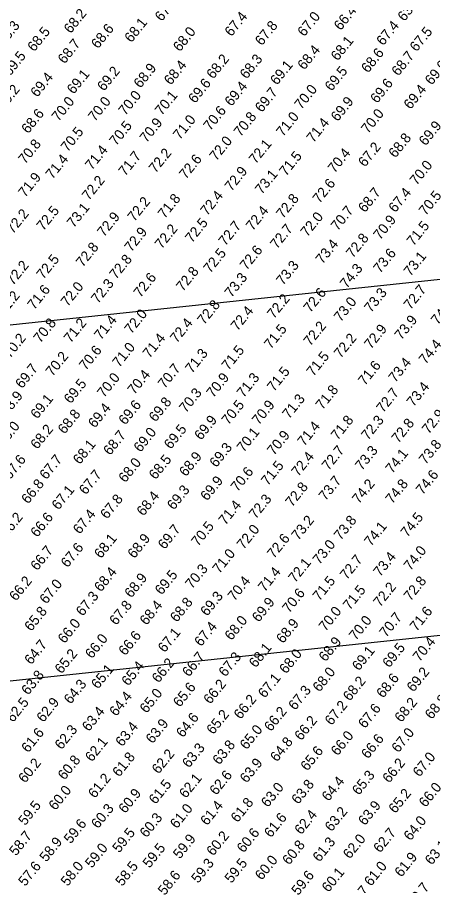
# Model space of a CAD drawing. Extents: x 401290 to 405690, y 1190598 to 1193998.
# Drawn here: x 403862 to 404273, y 1191942 to 1192801 of the extents above; entities that cross this region are included whole.
import ezdxf

# ---------------------------------------------------------------- set-up
doc = ezdxf.new("R2010")
doc.units = 0
for name, color, linetype in [('C-CHAN-CNTR', 7, 'Continuous'), ('C-CHAN-POIT', 7, 'Continuous'), ('V-TOPO-SOUN', 7, 'Continuous')]:
    doc.layers.add(name, color=color, linetype=linetype)

msp = doc.modelspace()

# ---------------------------------------------------------------- linework, layer by layer
at = {"layer": 'C-CHAN-CNTR'}
msp.add_line((401937.03, 1192293.37), (404340.86, 1192548.17), dxfattribs=at)
at = {"layer": 'C-CHAN-POIT'}
msp.add_line((402579.39, 1192009.5), (404317.15, 1192193.7), dxfattribs=at)

# ---------------------------------------------------------------- texts
at = {"layer": 'V-TOPO-SOUN'}
for s, p in [('67.9 ', (404005.19, 1192796.02)), ('63.4 ', (404245.19, 1192796.02)), ('68.2 ', (403915.2, 1192784.01)), ('67.4 ', (404074.19, 1192781.02)), ('67.0 ', (404146.2, 1192781.02)), ('66.4 ', (404182.19, 1192787.03)), ('68.1 ', (403975.17, 1192775.02)), ('67.4 ', (404224.19, 1192772.03)), ('68.3 ', (403849.19, 1192772.03)), ('68.5 ', (403879.18, 1192766.03)), ('68.6 ', (403942.2, 1192769.01)), ('68.0 ', (404023.17, 1192766.03)), ('67.8 ', (404104.18, 1192772.03)), ('67.5 ', (404257.19, 1192766.03)), ('68.7 ', (403909.2, 1192754.02)), ('68.1 ', (404179.18, 1192757.01)), ('68.4 ', (404146.2, 1192748.02)), ('69.5 ', (403855.19, 1192742.01)), ('68.2 ', (404056.18, 1192739.03)), ('68.3 ', (404089.18, 1192739.03)), ('68.6 ', (404209.19, 1192745.03)), ('68.7 ', (404239.18, 1192742.01)), ('68.9 ', (403984.2, 1192730)), ('68.4 ', (404014.18, 1192733.02)), ('69.1 ', (404119.2, 1192733.02)), ('69.0 ', (404272.19, 1192733.02)), ('69.4 ', (403882.19, 1192721.02)), ('69.1 ', (403918.19, 1192724.03)), ('69.2 ', (403948.17, 1192727.02)), ('69.5 ', (404173.17, 1192727.02)), ('69.6 ', (404038.2, 1192715.01)), ('69.4 ', (404074.19, 1192712.03)), ('69.6 ', (404218.18, 1192715.01)), ('69.2 ', (403849.19, 1192709.01)), ('69.7 ', (404104.18, 1192706.02)), ('70.0 ', (404143.18, 1192709.01)), ('69.4 ', (404251.19, 1192709.01)), ('70.0 ', (403903.19, 1192697.03)), ('70.0 ', (403939.18, 1192697.03)), ('70.0 ', (403969.2, 1192703.04)), ('70.1 ', (404005.19, 1192703.04)), ('69.9 ', (404179.18, 1192697.03)), ('70.6 ', (404053.19, 1192688.01)), ('68.6 ', (403873.17, 1192685.02)), ('71.0 ', (404023.17, 1192679.02)), ('70.8 ', (404083.18, 1192682.01)), ('71.0 ', (404125.17, 1192682.01)), ('70.0 ', (404209.19, 1192685.02)), ('70.5 ', (403960.18, 1192673.02)), ('70.9 ', (403990.2, 1192676.03)), ('71.4 ', (404155.19, 1192676.03)), ('69.9 ', (404266.18, 1192673.02)), ('70.5 ', (403912.18, 1192667.01)), ('68.8 ', (404236.2, 1192661.01)), ('70.8 ', (403870.19, 1192655)), ('72.0 ', (404059.2, 1192658.02)), ('72.1 ', (404098.17, 1192655)), ('67.2 ', (404206.18, 1192652.02)), ('71.4 ', (403936.2, 1192649.03)), ('71.7 ', (403969.2, 1192643.03)), ('72.2 ', (403999.19, 1192646.02)), ('71.5 ', (404128.19, 1192643.03)), ('70.4 ', (404176.19, 1192646.02)), ('71.4 ', (403897.19, 1192640.01)), ('72.6 ', (404029.18, 1192640.01)), ('72.9 ', (404074.19, 1192628.04)), ('70.0 ', (404257.19, 1192634.01)), ('71.9 ', (403870.19, 1192622.03)), ('72.2 ', (403933.18, 1192619.01)), ('73.1 ', (404104.18, 1192625.02)), ('72.6 ', (404161.2, 1192616.03)), ('71.8 ', (404008.18, 1192601.04)), ('72.4 ', (404050.17, 1192604.02)), ('72.8 ', (404125.17, 1192601.04)), ('68.7 ', (404206.18, 1192607.01)), ('67.4 ', (404236.2, 1192607.01)), ('70.5 ', (404266.18, 1192604.02)), ('72.2 ', (403978.19, 1192598.02)), ('72.2 ', (403858.18, 1192586.01)), ('72.5 ', (403888.2, 1192589.03)), ('73.1 ', (403918.19, 1192592.01)), ('72.4 ', (404095.19, 1192589.03)), ('70.7 ', (404179.18, 1192589.03)), ('72.9 ', (403948.17, 1192583.02)), ('72.5 ', (404035.18, 1192577.02)), ('72.7 ', (404068.18, 1192574.03)), ('72.0 ', (404149.19, 1192583.02)), ('70.9 ', (404221.2, 1192580)), ('72.9 ', (403975.17, 1192568.03)), ('72.2 ', (404005.19, 1192571.02)), ('72.7 ', (404119.2, 1192571.02)), ('71.5 ', (404254.18, 1192574.03)), ('72.8 ', (404194.2, 1192562.03)), ('72.8 ', (403927.17, 1192553.04)), ('72.6 ', (404089.18, 1192550.02)), ('73.4 ', (404164.18, 1192556.02)), ('72.5 ', (403888.2, 1192541.03)), ('72.8 ', (403960.18, 1192541.03)), ('72.5 ', (404053.19, 1192547.03)), ('73.6 ', (404221.2, 1192547.03)), ('73.1 ', (404251.19, 1192544.01)), ('72.2 ', (403858.18, 1192535.02)), ('73.3 ', (404125.17, 1192535.02)), ('74.3 ', (404188.2, 1192532.01)), ('72.6 ', (403984.2, 1192523.02)), ('72.8 ', (404026.19, 1192529.02)), ('72.3 ', (403942.2, 1192517.01)), ('73.3 ', (404074.19, 1192523.02)), ('71.6 ', (403879.18, 1192511.01)), ('72.0 ', (403912.18, 1192514.03)), ('72.6 ', (404152.17, 1192508.02)), ('73.3 ', (404212.18, 1192508.02)), ('72.7 ', (404251.19, 1192511.01)), ('71.2 ', (403849.19, 1192505.01)), ('72.2 ', (404116.18, 1192502.02)), ('73.0 ', (404182.19, 1192499.03)), ('72.8 ', (404047.19, 1192496.02)), ('72.4 ', (404080.19, 1192490.01)), ('74.9 ', (404278.19, 1192496.02)), ('71.4 ', (403945.19, 1192481.02)), ('72.0 ', (403975.17, 1192487.03)), ('73.9 ', (404242.2, 1192481.02)), ('70.8 ', (403885.18, 1192478.04)), ('71.2 ', (403915.2, 1192478.04)), ('72.4 ', (404020.19, 1192478.04)), ('71.5 ', (404113.2, 1192472.03)), ('72.2 ', (404152.17, 1192475.02)), ('72.9 ', (404212.18, 1192472.03)), ('71.4 ', (403993.18, 1192463.01)), ('70.2 ', (403855.19, 1192463.01)), ('72.2 ', (404182.19, 1192463.01)), ('74.4 ', (404266.18, 1192457.01)), ('70.6 ', (403930.19, 1192451.04)), ('71.0 ', (403963.2, 1192454.02)), ('71.3 ', (404035.18, 1192448.02)), ('71.5 ', (404071.17, 1192451.04)), ('70.2 ', (403897.19, 1192445.03)), ('71.5 ', (404155.19, 1192445.03)), ('73.4 ', (404236.2, 1192439.03)), ('69.7 ', (403867.2, 1192433.02)), ('70.7 ', (404008.18, 1192433.02)), ('71.5 ', (404116.18, 1192430.01)), ('71.6 ', (404206.18, 1192436.01)), ('70.0 ', (403948.17, 1192424.03)), ('70.4 ', (403978.19, 1192427.02)), ('70.9 ', (404056.18, 1192424.03)), ('71.3 ', (404086.2, 1192424.03)), ('69.5 ', (403915.2, 1192418.03)), ('71.8 ', (404164.18, 1192412.03)), ('73.4 ', (404254.18, 1192415.01)), ('68.9 ', (403852.17, 1192406.02)), ('70.3 ', (404029.18, 1192409.01)), ('71.3 ', (404131.18, 1192403.04)), ('72.7 ', (404224.19, 1192409.01)), ('69.1 ', (403882.19, 1192403.04)), ('69.6 ', (403969.2, 1192397.03)), ('69.8 ', (403999.19, 1192400.02)), ('70.5 ', (404071.17, 1192397.03)), ('70.9 ', (404101.19, 1192397.03)), ('68.8 ', (403909.2, 1192388.01)), ('69.4 ', (403939.18, 1192394.01)), ('72.9 ', (404269.2, 1192388.01)), ('69.9 ', (404044.2, 1192382.01)), ('71.8 ', (404179.18, 1192382.01)), ('72.3 ', (404209.19, 1192382.01)), ('72.8 ', (404239.18, 1192379.02)), ('68.0 ', (403849.19, 1192376.04)), ('68.2 ', (403882.19, 1192373.02)), ('69.0 ', (403984.2, 1192370.03)), ('69.5 ', (404014.18, 1192373.02)), ('70.1 ', (404086.2, 1192370.03)), ('71.4 ', (404146.2, 1192376.04)), ('68.7 ', (403954.18, 1192367.01)), ('70.9 ', (404116.18, 1192367.01)), ('68.1 ', (403924.19, 1192358.02)), ('69.3 ', (404059.2, 1192355.01)), ('72.7 ', (404170.19, 1192352.02)), ('73.3 ', (404203.19, 1192352.02)), ('73.8 ', (404266.18, 1192358.02)), ('67.6 ', (403855.19, 1192343.03)), ('67.7 ', (403891.18, 1192343.03)), ('68.5 ', (403999.19, 1192343.03)), ('68.9 ', (404029.18, 1192346.02)), ('72.4 ', (404140.2, 1192346.02)), ('74.1 ', (404233.18, 1192349.03)), ('68.0 ', (403969.2, 1192340.01)), ('71.5 ', (404110.18, 1192337.03)), ('67.7 ', (403930.19, 1192328.04)), ('70.6 ', (404080.19, 1192331.02)), ('74.6 ', (404263.2, 1192328.04)), ('66.8 ', (403873.17, 1192319.01)), ('69.9 ', (404050.17, 1192322.03)), ('73.7 ', (404167.2, 1192322.03)), ('74.2 ', (404200.17, 1192319.01)), ('74.8 ', (404233.18, 1192319.01)), ('67.1 ', (403903.19, 1192313.01)), ('69.3 ', (404017.2, 1192313.01)), ('72.8 ', (404134.2, 1192316.03)), ('67.8 ', (403951.19, 1192304.02)), ('68.4 ', (403987.18, 1192307.01)), ('72.3 ', (404098.17, 1192304.02)), ('71.4 ', (404068.18, 1192298.02)), ('66.2 ', (403852.17, 1192286.01)), ('66.6 ', (403882.19, 1192286.01)), ('67.4 ', (403924.19, 1192289.03)), ('73.2 ', (404140.2, 1192283.02)), ('73.8 ', (404182.19, 1192283.02)), ('74.5 ', (404248.17, 1192286.01)), ('69.7 ', (404008.18, 1192274.03)), ('70.5 ', (404041.18, 1192277.02)), ('74.1 ', (404212.18, 1192277.02)), ('72.0 ', (404086.2, 1192274.03)), ('68.1 ', (403945.19, 1192265.01)), ('68.9 ', (403978.19, 1192265.01)), ('72.6 ', (404116.18, 1192265.01)), ('73.0 ', (404161.2, 1192259.01)), ('66.7 ', (403882.19, 1192253.04)), ('67.6 ', (403912.18, 1192256.02)), ('71.0 ', (404062.18, 1192250.02)), ('74.0 ', (404251.19, 1192253.04)), ('72.1 ', (404137.18, 1192241.03)), ('72.7 ', (404188.2, 1192244.01)), ('73.4 ', (404221.2, 1192247.03)), ('68.4 ', (403945.19, 1192232.01)), ('70.3 ', (404035.18, 1192235.03)), ('71.4 ', (404107.19, 1192232.01)), ('66.2 ', (403861.2, 1192223.02)), ('68.9 ', (403975.17, 1192226.04)), ('69.5 ', (404005.19, 1192229.02)), ('70.4 ', (404077.17, 1192223.02)), ('71.5 ', (404161.2, 1192223.02)), ('72.8 ', (404251.19, 1192223.02)), ('67.0 ', (403891.18, 1192220.03)), ('71.5 ', (404191.18, 1192214.03)), ('72.2 ', (404221.2, 1192217.01)), ('67.3 ', (403927.17, 1192208.02)), ('69.3 ', (404050.17, 1192208.02)), ('70.6 ', (404131.18, 1192211.01)), ('67.8 ', (403960.18, 1192199.03)), ('68.4 ', (403990.2, 1192199.03)), ('68.8 ', (404020.19, 1192202.02)), ('69.9 ', (404101.19, 1192202.02)), ('65.8 ', (403876.19, 1192193.03)), ('70.0 ', (404167.2, 1192193.03)), ('71.6 ', (404257.19, 1192193.03)), ('66.0 ', (403909.2, 1192181.02)), ('68.0 ', (404074.19, 1192184.01)), ('68.9 ', (404125.17, 1192181.02)), ('70.0 ', (404197.19, 1192184.01)), ('70.7 ', (404227.17, 1192187.03)), ('67.1 ', (404008.18, 1192172.03)), ('67.4 ', (404044.2, 1192178)), ('66.0 ', (403936.2, 1192166.03)), ('66.6 ', (403969.2, 1192169.01)), ('68.9 ', (404167.2, 1192163.01)), ('70.4 ', (404260.18, 1192163.01)), ('64.7 ', (403876.19, 1192160.03)), ('68.1 ', (404098.17, 1192157.01)), ('69.5 ', (404230.19, 1192157.01)), ('65.2 ', (403906.18, 1192151.04)), ('66.7 ', (404032.19, 1192148.02)), ('67.3 ', (404068.18, 1192148.02)), ('68.0 ', (404128.19, 1192151.04)), ('69.1 ', (404200.17, 1192154.02)), ('65.4 ', (403972.19, 1192139.03)), ('66.2 ', (404002.17, 1192142.01)), ('63.8 ', (403873.17, 1192130.01)), ('65.1 ', (403942.2, 1192136.01)), ('68.0 ', (404161.2, 1192133.02)), ('69.2 ', (404254.18, 1192133.02)), ('64.3 ', (403915.2, 1192121.02)), ('66.2 ', (404053.19, 1192121.02)), ('67.1 ', (404107.19, 1192127.02)), ('68.2 ', (404191.18, 1192124.03)), ('68.6 ', (404224.19, 1192127.02)), ('65.0 ', (403990.2, 1192112.03)), ('65.6 ', (404023.17, 1192118.03)), ('67.3 ', (404137.18, 1192115.01)), ('62.5 ', (403858.18, 1192103)), ('62.9 ', (403888.2, 1192103)), ('64.4 ', (403960.18, 1192109.01)), ('66.2 ', (404083.18, 1192106.02)), ('68.2 ', (404242.2, 1192103)), ('68.8 ', (404272.19, 1192106.02)), ('63.4 ', (403933.18, 1192094.02)), ('66.2 ', (404113.2, 1192094.02)), ('67.2 ', (404173.17, 1192100.02)), ('67.6 ', (404206.18, 1192097.03)), ('64.6 ', (404026.19, 1192088.01)), ('65.2 ', (404056.18, 1192091.03)), ('63.4 ', (403966.18, 1192079.02)), ('63.9 ', (403996.17, 1192082.01)), ('66.2 ', (404143.18, 1192085.03)), ('61.6 ', (403873.17, 1192073.02)), ('62.3 ', (403906.18, 1192076.04)), ('65.0 ', (404089.18, 1192076.04)), ('66.0 ', (404179.18, 1192070.03)), ('67.0 ', (404239.18, 1192073.02)), ('62.1 ', (403936.2, 1192064.03)), ('63.8 ', (404062.18, 1192061.01)), ('64.8 ', (404119.2, 1192064.03)), ('66.6 ', (404209.19, 1192067.01)), ('62.2 ', (404002.17, 1192052.02)), ('63.3 ', (404032.19, 1192058.02)), ('65.6 ', (404149.19, 1192055.01)), ('60.2 ', (403870.19, 1192043.03)), ('60.8 ', (403909.2, 1192046.02)), ('61.8 ', (403963.2, 1192049.03)), ('63.9 ', (404089.18, 1192043.03)), ('66.2 ', (404230.19, 1192043.03)), ('67.0 ', (404260.18, 1192049.03)), ('61.2 ', (403939.18, 1192028)), ('62.1 ', (404029.18, 1192028)), ('62.6 ', (404059.2, 1192031.02)), ('65.3 ', (404200.17, 1192031.02)), ('61.5 ', (403999.19, 1192022.03)), ('63.0 ', (404110.18, 1192019.02)), ('63.8 ', (404140.2, 1192022.03)), ('64.4 ', (404170.19, 1192025.02)), ('66.0 ', (404266.18, 1192019.02)), ('60.0 ', (403900.17, 1192016.03)), ('60.9 ', (403969.2, 1192013.01)), ('65.2 ', (404236.2, 1192013.01)), ('59.5 ', (403870.19, 1192001.04)), ('61.4 ', (404050.17, 1192001.04)), ('61.8 ', (404080.19, 1192004.02)), ('63.9 ', (404206.18, 1192001.04)), ('60.3 ', (403942.2, 1191998.02)), ('61.0 ', (404020.19, 1191998.02)), ('62.4 ', (404143.18, 1191992.01)), ('63.2 ', (404173.17, 1191995.03)), ('59.6 ', (403915.2, 1191983.02)), ('60.3 ', (403990.2, 1191989.03)), ('61.6 ', (404113.2, 1191989.03)), ('64.0 ', (404251.19, 1191986.01)), ('59.5 ', (403963.2, 1191974.04)), ('60.6 ', (404086.2, 1191974.04)), ('62.7 ', (404221.2, 1191974.04)), ('58.7 ', (403861.2, 1191971.02)), ('59.9 ', (404023.17, 1191968.03)), ('60.2 ', (404056.18, 1191971.02)), ('62.0 ', (404191.18, 1191968.03)), ('58.9 ', (403891.18, 1191965.01)), ('59.0 ', (403936.2, 1191959.01)), ('59.5 ', (403993.18, 1191959.01)), ('60.8 ', (404131.18, 1191962.03)), ('61.3 ', (404161.2, 1191965.01)), ('63.1 ', (404272.19, 1191962.03)), ('61.9 ', (404242.2, 1191950.02)), ('57.6 ', (403870.19, 1191941.03)), ('58.0 ', (403912.18, 1191941.03)), ('58.5 ', (403966.18, 1191941.03)), ('59.3 ', (404041.18, 1191944.02)), ('59.5 ', (404074.19, 1191944.02)), ('60.0 ', (404104.18, 1191947.03)), ('61.0 ', (404212.18, 1191941.03)), ('58.6 ', (404008.18, 1191932.01)), ('59.6 ', (404140.2, 1191932.01)), ('60.1 ', (404170.19, 1191935.03)), ('59.7 ', (404194.2, 1191917.01)), ('60.7 ', (404254.18, 1191920.03))]:
    msp.add_text(s, height=9.996, rotation=51.05, dxfattribs=at).set_placement(p)

doc.saveas('drawing.dxf')
